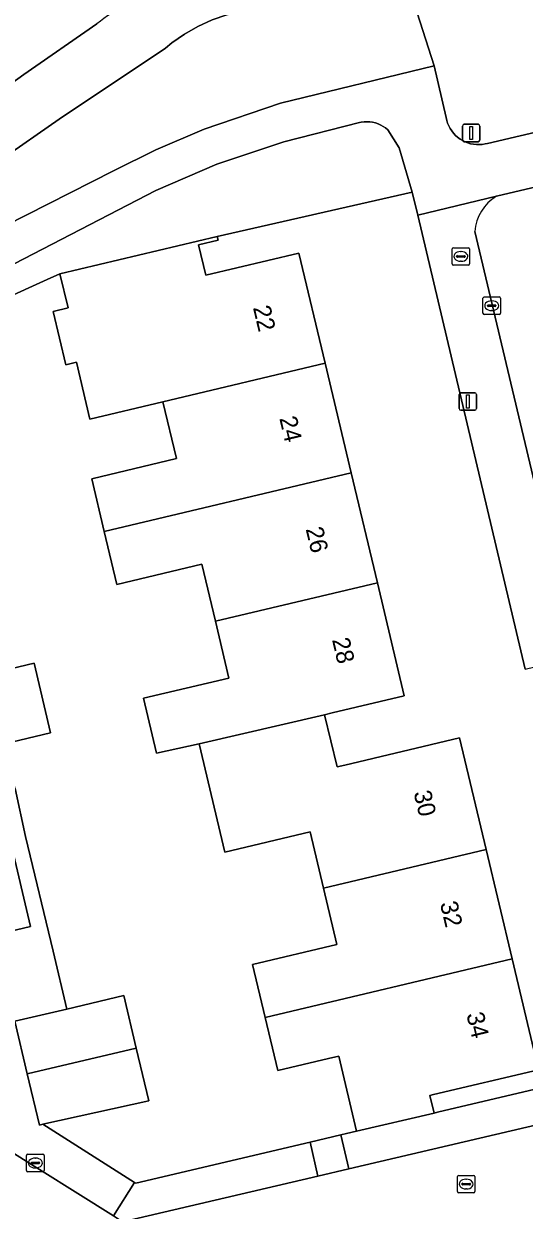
# Model space of a CAD drawing. Extents: x 157648 to 158502, y 379212 to 380938.
# Drawn here: x 158245.9 to 158274.5, y 380832.6 to 380900.4 of the extents above; entities that cross this region are included whole.
import ezdxf

# ---------------------------------------------------------------- set-up
doc = ezdxf.new("R2010")
doc.units = 0
for name, color, linetype in [('IMGEO_Berm_groen', 7, 'Continuous'), ('IMGEO_Erf', 7, 'Continuous'), ('IMGEO_Fietspad_gesloten', 7, 'Continuous'), ('IMGEO_Groenvoorziening', 7, 'Continuous'), ('IMGEO_Hek', 7, 'Continuous'), ('IMGEO_Kolk', 7, 'Continuous'), ('IMGEO_Lichtmast', 7, 'Continuous'), ('IMGEO_Muur', 7, 'Continuous'), ('IMGEO_Pand', 7, 'Continuous'), ('IMGEO_Pand_nummerreeks', 7, 'Continuous'), ('IMGEO_Parkeervlak_open', 7, 'Continuous'), ('IMGEO_Rijbaan_lokaal_open', 7, 'Continuous'), ('IMGEO_Rioolput', 7, 'Continuous'), ('IMGEO_Voetpad_open', 7, 'Continuous')]:
    doc.layers.add(name, color=color, linetype=linetype)

msp = doc.modelspace()

# ---------------------------------------------------------------- linework, layer by layer
at = {"layer": 'IMGEO_Berm_groen'}
for points in [[(158294.565, 380917.151), (158301.746, 380918.966), (158301.101, 380921.543), (158274.381, 380915.034), (158259.976, 380911.638), (158243.896, 380907.819), (158240.648, 380907.05), (158236.951, 380905.811), (158236.641, 380905.67), (158239.079, 380895.254), (158239.681, 380894.855), (158241.017, 380893.969), (158241.148, 380894.079), (158245.913, 380897.521), (158250.083, 380900.418)], [(158242.343, 380887.608), (158251.028, 380892.001), (158253.448, 380893.203), (158256.213, 380894.388), (158260.568, 380895.884), (158269.34, 380898.007), (158267.559, 380903.614), (158263.58, 380902.546), (158258.352, 380901.149), (158257.495, 380900.929), (158256.661, 380900.633), (158255.857, 380900.265), (158255.089, 380899.825), (158254.364, 380899.319), (158254.003, 380899.029), (158247.927, 380894.961), (158241.25, 380890.308)]]:
    msp.add_lwpolyline(points, dxfattribs=at)
msp.add_arc((158264.374, 380881.732), 23.525, 117.63917, 127.40851, dxfattribs=at)
at = {"layer": 'IMGEO_Erf'}
for points in [[(158322.824, 380874.128), (158329.137, 380875.485), (158330.023, 380875.673), (158333.116, 380876.321), (158333.958, 380876.539), (158339.994, 380877.978), (158340.698, 380875.022), (158341.402, 380872.065), (158349.853, 380874.088), (158346.186, 380889.71), (158345.53, 380892.503), (158345.428, 380892.696), (158338.808, 380906.132), (158329.517, 380903.935), (158272.901, 380890.549)], [(158274.546, 380863.519), (158268.406, 380889.479), (158268.099, 380890.778), (158256.958, 380888.253), (158257.007, 380888.049), (158255.888, 380887.783), (158256.301, 380886.042), (158261.622, 380887.306), (158263.12, 380881.005), (158264.612, 380874.733), (158266.104, 380868.455), (158267.642, 380861.988), (158263.528, 380861.01), (158263.087, 380860.905), (158263.797, 380857.918), (158264.237, 380858.023), (158270.794, 380859.582), (158272.313, 380853.194), (158273.799, 380846.941), (158275.308, 380840.596), (158269.304, 380839.186), (158269.109, 380839.14), (158269.347, 380838.127), (158269.541, 380838.173), (158281.675, 380841.04)], [(158271.67, 380888.542), (158276.061, 380869.995), (158278.992, 380870.719), (158280.865, 380862.903), (158283.487, 380851.735), (158284.011, 380851.861), (158287.022, 380852.583), (158296.964, 380854.965), (158302.979, 380856.415), (158306.319, 380857.198), (158304.505, 380864.386), (158311.038, 380865.902), (158310.747, 380866.984), (158310.518, 380867.976), (158317.607, 380869.639), (158323.546, 380871.047), (158322.824, 380874.128)], [(158245.406, 380856.682), (158245.997, 380853.936), (158247.588, 380847.376), (158248.365, 380844.076), (158251.626, 380844.844), (158252.334, 380841.837), (158253.042, 380838.831), (158247.001, 380837.483), (158252.238, 380834.159), (158252.315, 380834.11), (158262.259, 380836.459), (158264.02, 380836.875), (158264.34, 380836.951), (158264.902, 380837.084), (158263.893, 380841.381), (158263.319, 380841.244), (158260.417, 380840.554), (158259.695, 380843.59), (158258.974, 380846.624), (158263.792, 380847.77), (158263.027, 380850.988), (158262.262, 380854.204), (158257.394, 380853.046), (158255.921, 380859.242), (158253.496, 380858.704), (158252.75, 380861.843), (158257.624, 380863.002), (158256.85, 380866.255), (158256.076, 380869.511), (158251.222, 380868.357), (158250.504, 380871.378), (158249.786, 380874.399), (158254.621, 380875.549), (158253.848, 380878.8), (158249.688, 380877.811), (158248.916, 380881.059), (158248.302, 380880.913), (158247.576, 380883.967), (158248.433, 380884.171), (158247.97, 380886.122), (158247.233, 380885.787), (158242.337, 380883.563)], [(158243.858, 380863.23), (158246.495, 380863.853), (158247.438, 380859.863), (158244.802, 380859.24)]]:
    msp.add_lwpolyline(points, dxfattribs=at)
msp.add_arc((158274.231, 380888.352), 2.568, 121.19136, 175.76263, dxfattribs=at)
at = {"layer": 'IMGEO_Fietspad_gesloten'}
for points in [[(158241.25, 380890.308), (158247.927, 380894.961), (158254.003, 380899.029), (158254.364, 380899.319), (158255.089, 380899.825), (158255.857, 380900.265), (158256.661, 380900.633), (158257.495, 380900.929), (158258.352, 380901.149), (158263.58, 380902.546), (158267.559, 380903.614), (158275.544, 380906.243), (158284.987, 380910.398), (158289.196, 380912.09), (158295.485, 380914.082), (158312.357, 380918.233), (158325.851, 380921.486), (158325.082, 380924.481), (158317.342, 380922.582), (158305.945, 380920.027), (158301.746, 380918.966), (158294.565, 380917.151)], [(158250.083, 380900.418), (158245.913, 380897.521), (158241.148, 380894.079), (158241.017, 380893.969)]]:
    msp.add_lwpolyline(points, dxfattribs=at)
msp.add_arc((158264.374, 380881.732), 23.525, 117.63917, 127.40851, dxfattribs=at)
at = {"layer": 'IMGEO_Groenvoorziening'}
for points in [[(158267.559, 380903.614), (158269.34, 380898.007), (158270.03, 380895.05), (158270.066, 380894.887), (158270.116, 380894.728), (158270.18, 380894.574), (158270.258, 380894.426), (158270.348, 380894.286), (158270.451, 380894.155), (158270.565, 380894.033), (158270.689, 380893.922), (158270.823, 380893.823), (158270.965, 380893.735), (158271.114, 380893.661), (158271.27, 380893.601), (158271.43, 380893.554), (158271.594, 380893.523), (158271.76, 380893.505), (158271.926, 380893.503), (158272.093, 380893.516), (158272.257, 380893.543), (158272.387, 380893.576), (158293.569, 380898.544), (158311.442, 380902.774)], [(158268.099, 380890.778), (158267.344, 380893.317), (158266.703, 380894.353), (158266.576, 380894.456), (158266.439, 380894.548), (158266.296, 380894.627), (158266.145, 380894.692), (158265.99, 380894.744), (158265.83, 380894.782), (158265.668, 380894.806), (158265.504, 380894.815), (158265.34, 380894.809), (158265.178, 380894.789), (158265.077, 380894.769), (158260.766, 380893.662), (158256.936, 380892.387), (158253.447, 380890.878), (158244.278, 380886.139)], [(158163.153, 380865.08), (158163.573, 380863.242), (158163.827, 380862.151), (158230.016, 380877.859), (158232.968, 380878.575), (158235.923, 380879.293), (158238.576, 380879.936), (158238.897, 380880.014), (158238.886, 380880.212), (158238.465, 380881.749), (158241.901, 380883.359), (158242.337, 380883.563), (158247.233, 380885.787), (158247.97, 380886.122), (158256.958, 380888.253), (158268.099, 380890.778)]]:
    msp.add_lwpolyline(points, dxfattribs=at)
at = {"layer": 'IMGEO_Hek'}
for points in [[(158248.365, 380844.076), (158247.588, 380847.376)], [(158247.001, 380837.483), (158252.238, 380834.159)], [(158262.259, 380836.459), (158264.02, 380836.875)], [(158264.02, 380836.875), (158264.34, 380836.951)], [(158264.34, 380836.951), (158264.902, 380837.084)], [(158252.238, 380834.159), (158252.315, 380834.11), (158262.259, 380836.459)]]:
    msp.add_lwpolyline(points, dxfattribs=at)
at = {"layer": 'IMGEO_Kolk'}
for p, q in [((158272.134, 380883.866), (158272.134, 380884.718)), ((158272.209, 380884.792), (158273.061, 380884.792)), ((158272.393, 380884.286), (158272.393, 380884.298)), ((158272.831, 380884.249), (158272.433, 380884.249)), ((158272.436, 380884.335), (158272.834, 380884.335)), ((158272.622, 380884.572), (158272.647, 380884.572)), ((158272.877, 380884.298), (158272.877, 380884.286)), ((158273.135, 380884.718), (158273.135, 380883.866)), ((158273.061, 380883.792), (158272.209, 380883.792)), ((158272.645, 380884.012), (158272.62, 380884.012)), ((158270.675, 380833.639), (158270.675, 380834.491)), ((158270.75, 380834.565), (158271.602, 380834.565)), ((158270.934, 380834.059), (158270.934, 380834.071)), ((158271.372, 380834.022), (158270.974, 380834.022)), ((158270.977, 380834.108), (158271.375, 380834.108)), ((158271.163, 380834.345), (158271.188, 380834.345)), ((158271.418, 380834.071), (158271.418, 380834.059)), ((158271.676, 380834.491), (158271.676, 380833.639)), ((158271.602, 380833.565), (158270.75, 380833.565)), ((158271.186, 380833.785), (158271.161, 380833.785))]:
    msp.add_line(p, q, dxfattribs=at)
for points in [[(158272.134, 380883.866), (158272.134, 380884.718)], [(158272.209, 380884.792), (158273.061, 380884.792)], [(158273.135, 380884.718), (158273.135, 380883.866)], [(158273.061, 380883.792), (158272.209, 380883.792)], [(158270.675, 380833.639), (158270.675, 380834.491)], [(158270.75, 380834.565), (158271.602, 380834.565)], [(158271.676, 380834.491), (158271.676, 380833.639)], [(158271.602, 380833.565), (158270.75, 380833.565)]]:
    msp.add_lwpolyline(points, dxfattribs=at)
for centre, radius, start, end in [((158272.211, 380884.716), 0.0765, 91.55205, 178.44795), ((158272.211, 380884.716), 0.0765, 91.55205, 178.44795), ((158272.433, 380884.295), 0.0403, 85.87752, 175.75265), ((158272.43, 380884.285), 0.0366, 178.93798, 274.71019), ((158272.834, 380884.292), 0.043, 264.86636, 352.45326), ((158272.838, 380884.297), 0.0386, 1.73085, 96.63898), ((158273.059, 380884.716), 0.0765, 1.55205, 88.44795), ((158273.059, 380884.716), 0.0765, 1.55205, 88.44795), ((158272.211, 380883.868), 0.0765, 181.55205, 268.44795), ((158272.211, 380883.868), 0.0765, 181.55205, 268.44795), ((158273.059, 380883.868), 0.0765, 271.55205, 358.44795), ((158273.059, 380883.868), 0.0765, 271.55205, 358.44795), ((158270.752, 380834.489), 0.0765, 91.55205, 178.44795), ((158270.752, 380834.489), 0.0765, 91.55205, 178.44795), ((158270.974, 380834.068), 0.0403, 85.87752, 175.75265), ((158270.971, 380834.058), 0.0366, 178.93798, 274.71019), ((158271.375, 380834.065), 0.043, 264.86636, 352.45326), ((158271.379, 380834.07), 0.0386, 1.73085, 96.63898), ((158271.6, 380834.489), 0.0765, 1.55205, 88.44795), ((158271.6, 380834.489), 0.0765, 1.55205, 88.44795), ((158270.752, 380833.641), 0.0765, 181.55205, 268.44795), ((158270.752, 380833.641), 0.0765, 181.55205, 268.44795), ((158271.6, 380833.641), 0.0765, 271.55205, 358.44795), ((158271.6, 380833.641), 0.0765, 271.55205, 358.44795)]:
    msp.add_arc(centre, radius, start, end, dxfattribs=at)
for centre, major_axis, ratio, start_param, end_param in [((158272.621, 380884.292), (-0.387, 0.002), 0.722429, 4.712389, 7.853982), ((158272.646, 380884.292), (-0.39, 0.002), 0.717154, 1.570796, 4.712389), ((158271.162, 380834.065), (-0.387, 0.002), 0.722429, 4.712389, 7.853982), ((158271.187, 380834.065), (-0.39, 0.002), 0.717154, 1.570796, 4.712389)]:
    msp.add_ellipse(centre, major_axis=major_axis, ratio=ratio, start_param=start_param, end_param=end_param, dxfattribs=at)
at = {"layer": 'IMGEO_Lichtmast'}
for p, q in [((158270.966, 380893.768), (158270.966, 380894.568)), ((158270.966, 380894.568), (158270.966, 380893.768)), ((158271.066, 380894.668), (158271.856, 380894.668)), ((158271.856, 380894.668), (158271.066, 380894.668)), ((158271.956, 380894.568), (158271.956, 380893.768)), ((158271.956, 380893.768), (158271.956, 380894.568)), ((158271.856, 380893.668), (158271.066, 380893.668)), ((158271.066, 380893.668), (158271.856, 380893.668)), ((158270.771, 380878.415), (158270.771, 380879.215)), ((158270.771, 380879.215), (158270.771, 380878.415)), ((158270.871, 380879.315), (158271.661, 380879.315)), ((158271.661, 380879.315), (158270.871, 380879.315)), ((158271.761, 380879.215), (158271.761, 380878.415)), ((158271.761, 380878.415), (158271.761, 380879.215)), ((158271.661, 380878.315), (158270.871, 380878.315)), ((158270.871, 380878.315), (158271.661, 380878.315))]:
    msp.add_line(p, q, dxfattribs=at)
for points in [[(158271.386, 380894.543), (158271.536, 380894.543), (158271.536, 380893.793), (158271.386, 380893.793), (158271.386, 380894.543)], [(158271.191, 380879.19), (158271.341, 380879.19), (158271.341, 380878.44), (158271.191, 380878.44), (158271.191, 380879.19)]]:
    msp.add_lwpolyline(points, dxfattribs=at)
for centre, start, end in [((158271.066, 380894.568), 90, 180), ((158271.066, 380894.568), 90, 180), ((158271.856, 380894.568), 0, 90), ((158271.856, 380894.568), 360, 90), ((158271.066, 380893.768), 180, 270), ((158271.066, 380893.768), 180, 270), ((158271.856, 380893.768), 270, 0), ((158271.856, 380893.768), 270, 0), ((158270.871, 380879.215), 90, 180), ((158270.871, 380879.215), 90, 180), ((158271.661, 380879.215), 0, 90), ((158271.661, 380879.215), 360, 90), ((158270.871, 380878.415), 180, 270), ((158270.871, 380878.415), 180, 270), ((158271.661, 380878.415), 270, 0), ((158271.661, 380878.415), 270, 0)]:
    msp.add_arc(centre, 0.1, start, end, dxfattribs=at)
at = {"layer": 'IMGEO_Muur'}
msp.add_lwpolyline([(158247.588, 380847.376), (158245.997, 380853.936)], dxfattribs=at)
at = {"layer": 'IMGEO_Pand'}
for points in [[(158263.12, 380881.005), (158261.622, 380887.306), (158256.301, 380886.042), (158255.888, 380887.783), (158257.007, 380888.049), (158256.958, 380888.253), (158247.97, 380886.122), (158248.433, 380884.171), (158247.576, 380883.967), (158248.302, 380880.913), (158248.916, 380881.059), (158249.688, 380877.811), (158253.848, 380878.8)], [(158250.504, 380871.378), (158264.612, 380874.733), (158263.12, 380881.005), (158253.848, 380878.8), (158254.621, 380875.549), (158249.786, 380874.399)], [(158250.504, 380871.378), (158251.222, 380868.357), (158256.076, 380869.511), (158256.85, 380866.255), (158266.104, 380868.455), (158264.612, 380874.733)], [(158256.85, 380866.255), (158257.624, 380863.002), (158252.75, 380861.843), (158253.496, 380858.704), (158255.921, 380859.242), (158263.087, 380860.905), (158263.528, 380861.01), (158267.642, 380861.988), (158266.104, 380868.455)], [(158244.802, 380859.24), (158247.438, 380859.863), (158246.495, 380863.853), (158243.858, 380863.23)], [(158272.313, 380853.194), (158270.794, 380859.582), (158264.237, 380858.023), (158263.797, 380857.918), (158263.087, 380860.905), (158255.921, 380859.242), (158257.394, 380853.046), (158262.262, 380854.204), (158263.027, 380850.988)], [(158272.313, 380853.194), (158263.027, 380850.988), (158263.792, 380847.77), (158258.974, 380846.624), (158259.695, 380843.59), (158273.799, 380846.941)], [(158273.799, 380846.941), (158259.695, 380843.59), (158260.417, 380840.554), (158263.319, 380841.244), (158263.893, 380841.381), (158264.902, 380837.084), (158269.347, 380838.127), (158269.109, 380839.14), (158269.304, 380839.186), (158275.308, 380840.596)], [(158252.334, 380841.837), (158251.626, 380844.844), (158248.365, 380844.076), (158245.396, 380843.377), (158246.104, 380840.37)], [(158252.334, 380841.837), (158246.104, 380840.37), (158246.795, 380837.437), (158247.001, 380837.483), (158253.042, 380838.831)]]:
    msp.add_lwpolyline(points, close=True, dxfattribs=at)
at = {"layer": 'IMGEO_Parkeervlak_open'}
for points in [[(158242.114, 380847.802), (158246.294, 380848.786), (158245.164, 380853.578), (158240.979, 380852.604)], [(158264.466, 380834.939), (158282.13, 380839.078), (158281.675, 380841.04), (158269.541, 380838.173), (158269.347, 380838.127), (158264.902, 380837.084), (158264.34, 380836.951), (158264.02, 380836.875)], [(158262.259, 380836.459), (158252.315, 380834.11), (158252.238, 380834.159), (158251.024, 380832.251), (158251.543, 380831.91), (158262.698, 380834.525)]]:
    msp.add_lwpolyline(points, close=True, dxfattribs=at)
at = {"layer": 'IMGEO_Rijbaan_lokaal_open'}
msp.add_lwpolyline([(158335.368, 380870.628), (158334.663, 380873.585), (158334.173, 380875.639), (158326.838, 380874.024), (158324.642, 380870.454), (158323.37, 380870.177), (158323.395, 380870.062), (158311.628, 380867.312), (158313.386, 380859.917), (158311.51, 380857.513), (158287.237, 380851.686), (158284.341, 380839.582), (158282.13, 380839.078), (158264.466, 380834.939), (158262.698, 380834.525), (158251.543, 380831.91), (158251.024, 380832.251), (158244.769, 380836.177)], dxfattribs=at)
at = {"layer": 'IMGEO_Rioolput'}
for p, q in [((158270.447, 380887.612), (158271.299, 380887.612)), ((158270.372, 380886.686), (158270.372, 380887.538)), ((158270.631, 380887.106), (158270.631, 380887.118)), ((158271.069, 380887.069), (158270.671, 380887.069)), ((158270.674, 380887.155), (158271.072, 380887.155)), ((158270.86, 380887.392), (158270.885, 380887.392)), ((158271.115, 380887.118), (158271.115, 380887.106)), ((158271.373, 380887.538), (158271.373, 380886.686)), ((158271.299, 380886.612), (158270.447, 380886.612)), ((158270.883, 380886.832), (158270.858, 380886.832)), ((158246.066, 380834.844), (158246.066, 380835.696)), ((158246.141, 380835.77), (158246.993, 380835.77)), ((158246.554, 380835.55), (158246.579, 380835.55)), ((158247.067, 380835.696), (158247.067, 380834.844)), ((158246.993, 380834.77), (158246.141, 380834.77)), ((158246.325, 380835.264), (158246.325, 380835.276)), ((158246.763, 380835.227), (158246.365, 380835.227)), ((158246.368, 380835.313), (158246.766, 380835.313)), ((158246.577, 380834.99), (158246.552, 380834.99)), ((158246.809, 380835.276), (158246.809, 380835.264))]:
    msp.add_line(p, q, dxfattribs=at)
for points in [[(158270.447, 380887.612), (158271.299, 380887.612)], [(158270.372, 380886.686), (158270.372, 380887.538)], [(158271.373, 380887.538), (158271.373, 380886.686)], [(158271.299, 380886.612), (158270.447, 380886.612)], [(158246.066, 380834.844), (158246.066, 380835.696)], [(158246.141, 380835.77), (158246.993, 380835.77)], [(158247.067, 380835.696), (158247.067, 380834.844)], [(158246.993, 380834.77), (158246.141, 380834.77)]]:
    msp.add_lwpolyline(points, dxfattribs=at)
for centre, radius, start, end in [((158270.449, 380887.536), 0.0765, 91.55205, 178.44795), ((158270.449, 380887.536), 0.0765, 91.55205, 178.44795), ((158271.297, 380887.536), 0.0765, 1.55205, 88.44795), ((158271.297, 380887.536), 0.0765, 1.55205, 88.44795), ((158270.671, 380887.115), 0.0403, 85.87752, 175.75265), ((158270.668, 380887.105), 0.0366, 178.93798, 274.71019), ((158271.072, 380887.112), 0.043, 264.86636, 352.45326), ((158271.076, 380887.117), 0.0386, 1.73085, 96.63898), ((158270.449, 380886.688), 0.0765, 181.55205, 268.44795), ((158270.449, 380886.688), 0.0765, 181.55205, 268.44795), ((158271.297, 380886.688), 0.0765, 271.55205, 358.44795), ((158271.297, 380886.688), 0.0765, 271.55205, 358.44795), ((158246.143, 380835.694), 0.0765, 91.55205, 178.44795), ((158246.143, 380835.694), 0.0765, 91.55205, 178.44795), ((158246.991, 380835.694), 0.0765, 1.55205, 88.44795), ((158246.991, 380835.694), 0.0765, 1.55205, 88.44795), ((158246.143, 380834.846), 0.0765, 181.55205, 268.44795), ((158246.143, 380834.846), 0.0765, 181.55205, 268.44795), ((158246.365, 380835.273), 0.0403, 85.87752, 175.75265), ((158246.362, 380835.263), 0.0366, 178.93798, 274.71019), ((158246.766, 380835.27), 0.043, 264.86636, 352.45326), ((158246.77, 380835.275), 0.0386, 1.73085, 96.63898), ((158246.991, 380834.846), 0.0765, 271.55205, 358.44795), ((158246.991, 380834.846), 0.0765, 271.55205, 358.44795)]:
    msp.add_arc(centre, radius, start, end, dxfattribs=at)
for centre, major_axis, ratio, start_param, end_param in [((158270.859, 380887.112), (-0.387, 0.002), 0.722429, 4.712389, 7.853982), ((158270.884, 380887.112), (-0.39, 0.002), 0.717154, 1.570796, 4.712389), ((158246.553, 380835.27), (-0.387, 0.002), 0.722429, 4.712389, 7.853982), ((158246.578, 380835.27), (-0.39, 0.002), 0.717154, 1.570796, 4.712389)]:
    msp.add_ellipse(centre, major_axis=major_axis, ratio=ratio, start_param=start_param, end_param=end_param, dxfattribs=at)
at = {"layer": 'IMGEO_Voetpad_open'}
for points in [[(158244.278, 380886.139), (158253.447, 380890.878), (158256.936, 380892.387), (158260.766, 380893.662), (158265.077, 380894.769), (158265.178, 380894.789), (158265.34, 380894.809), (158265.504, 380894.815), (158265.668, 380894.806), (158265.83, 380894.782), (158265.99, 380894.744), (158266.145, 380894.692), (158266.296, 380894.627), (158266.439, 380894.548), (158266.576, 380894.456), (158266.703, 380894.353), (158267.344, 380893.317), (158268.099, 380890.778), (158268.406, 380889.479), (158272.901, 380890.549), (158329.517, 380903.935)], [(158293.569, 380898.544), (158272.387, 380893.576), (158272.257, 380893.543), (158272.093, 380893.516), (158271.926, 380893.503), (158271.76, 380893.505), (158271.594, 380893.523), (158271.43, 380893.554), (158271.27, 380893.601), (158271.114, 380893.661), (158270.965, 380893.735), (158270.823, 380893.823), (158270.689, 380893.922), (158270.565, 380894.033), (158270.451, 380894.155), (158270.348, 380894.286), (158270.258, 380894.426), (158270.18, 380894.574), (158270.116, 380894.728), (158270.066, 380894.887), (158270.03, 380895.05), (158269.34, 380898.007), (158260.568, 380895.884), (158256.213, 380894.388), (158253.448, 380893.203), (158251.028, 380892.001), (158242.343, 380887.608)], [(158272.901, 380890.549), (158268.406, 380889.479), (158274.546, 380863.519), (158277.477, 380864.209), (158282.851, 380841.317), (158281.675, 380841.04), (158282.13, 380839.078), (158284.341, 380839.582), (158287.237, 380851.686), (158287.022, 380852.583), (158284.011, 380851.861), (158283.487, 380851.735), (158280.865, 380862.903), (158278.992, 380870.719), (158276.061, 380869.995), (158271.67, 380888.542)]]:
    msp.add_lwpolyline(points, dxfattribs=at)
for points in [[(158248.365, 380844.076), (158247.588, 380847.376), (158245.997, 380853.936), (158245.406, 380856.682), (158244.802, 380859.24), (158243.858, 380863.23), (158243.027, 380866.846), (158242.147, 380866.636), (158242.434, 380865.423), (158244.113, 380858.126), (158239.919, 380857.157), (158240.979, 380852.604), (158245.164, 380853.578), (158246.294, 380848.786), (158242.114, 380847.802), (158244.769, 380836.177), (158251.024, 380832.251), (158252.238, 380834.159), (158247.001, 380837.483), (158246.795, 380837.437), (158246.104, 380840.37), (158245.396, 380843.377)], [(158262.698, 380834.525), (158264.466, 380834.939), (158264.02, 380836.875), (158262.259, 380836.459)]]:
    msp.add_lwpolyline(points, close=True, dxfattribs=at)
msp.add_arc((158274.231, 380888.352), 2.568, 121.19136, 175.76263, dxfattribs=at)

# ---------------------------------------------------------------- texts
at = {"layer": 'IMGEO_Pand_nummerreeks'}
for s, rotation, p in [('22', 283.37516, (158258.991, 380884.188)), ('24', 283.37516, (158260.497, 380877.857)), ('26', 283.37516, (158262.002, 380871.527)), ('28', 283.37516, (158263.508, 380865.195)), ('30', 283.37322, (158268.166, 380856.453)), ('32', 283.37322, (158269.672, 380850.117)), ('34', 283.37322, (158271.181, 380843.773))]:
    msp.add_text(s, height=1, rotation=rotation, dxfattribs=at).set_placement(p)

doc.saveas('drawing.dxf')
